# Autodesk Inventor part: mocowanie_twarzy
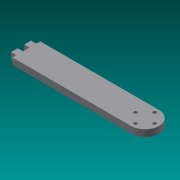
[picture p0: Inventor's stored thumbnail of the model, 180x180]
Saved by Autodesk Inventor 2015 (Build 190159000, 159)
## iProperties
Created: 2016-02
Part Number: mocowanie_twarzy
Material: Generic
Document SubType Name: Modeling
Designer: Rafał
Density: 1 g/cm^3
Appearance: Default
Author: Rafał
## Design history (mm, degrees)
sketch "Sketch1" dims "d3" = 14.5
  geometry: L1 (-10.5, 0)-(-100, 0); L2 (-100, 21)-(-10.5, 21); L3 (0, 21)-(0, 0); L4 (0, 10.5)-(-100, 10.5); L5 (0, 10.5)-(-10.5, 10.5); L6 (-100, 13)-(-104, 13); L7 (-104, 13)-(-104, 18); L8 (-104, 18)-(-100, 18); L9 (-100, 18)-(-100, 13); L10 (-100, 8)-(-104, 8); L11 (-104, 8)-(-104, 3); L12 (-104, 3)-(-100, 3); L13 (-100, 0)-(-100, 3); L14 (-100, 8)-(-100, 13); L15 (-100, 18)-(-100, 21); C1 r 1.25 at (-3.25, 10.5); C2 r 1.25 at (-10.5, 17.75); C3 r 1.25 at (-17.75, 10.5); C4 r 1.25 at (-10.5, 3.25); A1 r 10.5 centre (-10.5, 10.5) between (-10.5, 0) and (-10.5, 21); 1 further point
  constraints: 30 end point, 6 parallel, 5 centre point, 4 perpendicular, 4 symmetric about line, 3 point on circle, 2 coincident, 2 horizontal, 2 midpoint, 2 point on line, 1 horizontal alignment, 11 other
  dimensions: "d0" = 100 distance of L2.start L3.start; "d1" = 21 distance of L1.end L2.start; "d2" = 10.5 distance of L4.start L5.end; "d4" = 2.5 diameter of C1; "d7" = 360 deg dimension on L5.end C1.centre (derived); "d9" = 4 distance of L7.end L8.end; "d10" = 5 distance of L6.end L7.end; "d11" = 2.5 distance between parallel lines of L6 L4
extrude "Extrusion1" new body sketch "Sketch1" distance "d12" = 5; taper "d13" = 0 deg
body "Solid1"
